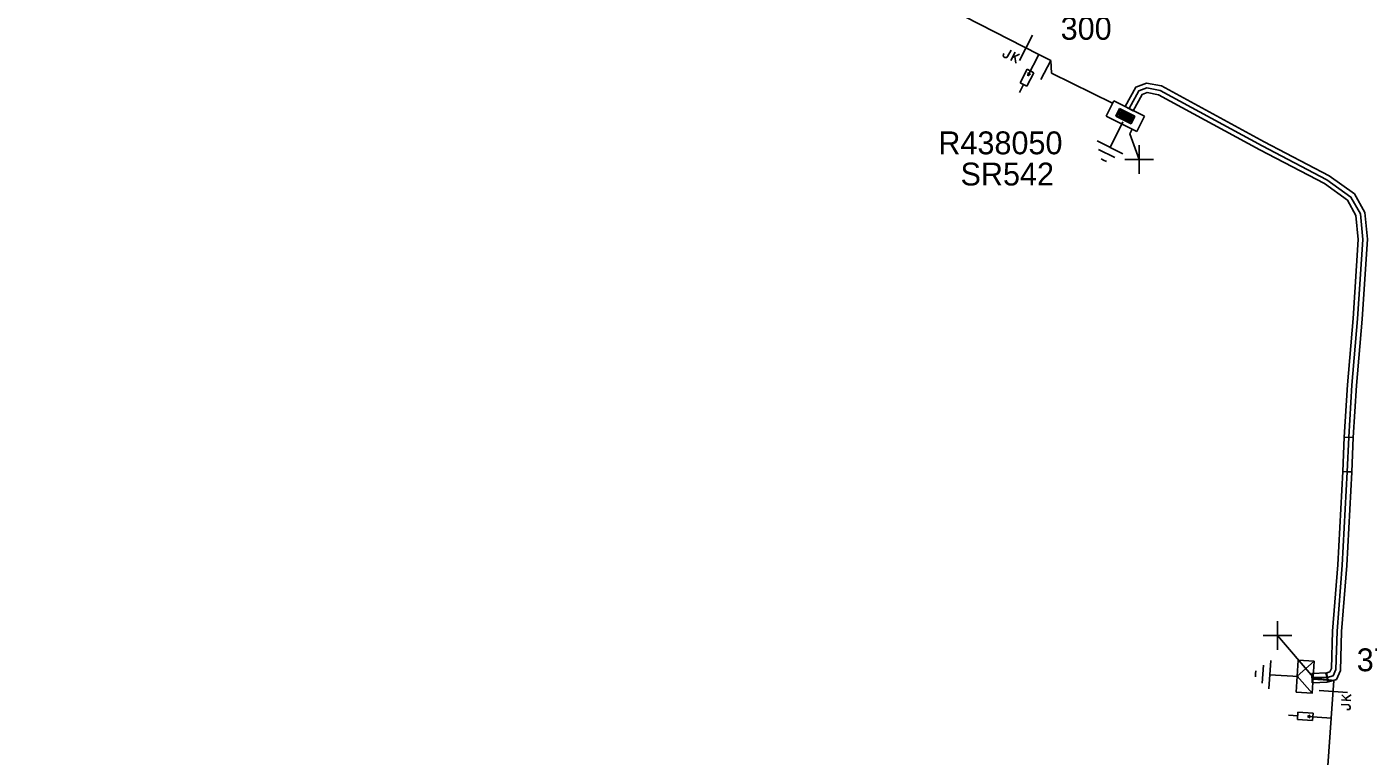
# Model space of a CAD drawing. Extents: x -540466 to -537383, y -1184038 to -1179972.
# Drawn here: x -537995.3 to -537936.6, y -1180751.6 to -1180719.7 of the extents above; entities that cross this region are included whole.
import ezdxf

# ---------------------------------------------------------------- set-up
doc = ezdxf.new("R2010")
doc.units = 0
for name, color, linetype in [('Vrstva 1', 7, 'Continuous'), ('Vrstva 13', 7, 'Continuous'), ('Vrstva 14', 7, 'Continuous'), ('Vrstva 15', 7, 'Continuous'), ('Vrstva 16', 7, 'Continuous'), ('Vrstva 18', 7, 'Continuous'), ('Vrstva 2', 7, 'Continuous'), ('Vrstva 20', 7, 'Continuous'), ('Vrstva 28', 7, 'Continuous'), ('Vrstva 29', 7, 'Continuous'), ('Vrstva 30', 7, 'Continuous'), ('Vrstva 31', 7, 'Continuous'), ('Vrstva 34', 7, 'Continuous'), ('Vrstva 5', 7, 'Continuous'), ('Vrstva 50', 7, 'Continuous'), ('Vrstva 59', 7, 'Continuous'), ('Vrstva 8', 7, 'Continuous'), ('Vrstva 9', 7, 'Continuous')]:
    doc.layers.add(name, color=color, linetype=linetype)

# ---------------------------------------------------------------- blocks, each defined once
blk = doc.blocks.new('NN840')
at = {"layer": 'Vrstva 15'}
for points in [[(0.003, 0.619), (0.003, -0.631)], [(-0.538, -0.385), (-0.538, -0.71)], [(-0.332, -0.385), (-0.332, -0.798)], [(-0.332, -0.641), (-0.125, -0.385)], [(-0.263, -0.557), (-0.091, -0.798)], [(-0.745, -0.71), (-0.745, -0.66)], [(-0.73, -0.764), (-0.745, -0.71)], [(-0.657, -0.798), (-0.73, -0.764)], [(-0.627, -0.798), (-0.657, -0.798)], [(-0.558, -0.764), (-0.627, -0.798)], [(-0.538, -0.71), (-0.558, -0.764)]]:
    blk.add_lwpolyline(points, dxfattribs=at)
blk = doc.blocks.new('NN800')
at = {"layer": 'Vrstva 1'}
for points in [[(-0.442, 0.442), (0.442, -0.442)], [(-0.442, -0.442), (0.442, 0.442)]]:
    blk.add_lwpolyline(points, dxfattribs=at)
blk = doc.blocks.new('NN820')
at = {"layer": 'Vrstva 13'}
for points in [[(-0.003, 0.004), (-0.003, -1.049)], [(-0.165, -0.813), (0.165, -0.813)], [(-0.165, -1.473), (-0.165, -0.813)], [(-0.003, -1.049), (-0.062, -0.926)], [(-0.003, -1.049), (0.057, -0.926)], [(0.165, -0.813), (0.165, -1.473)], [(0.165, -1.473), (-0.165, -1.473)], [(-0.003, -1.473), (-0.003, -1.871)]]:
    blk.add_lwpolyline(points, dxfattribs=at)
blk = doc.blocks.new('NN620')
at = {"layer": 'Vrstva 8'}
for points in [[(0.752, 0.004), (-0.748, 0.004)], [(-0.748, 0.004), (-0.748, -0.746)], [(0.752, -0.746), (0.752, 0.004)], [(0.368, -0.18), (-0.376, -0.18)], [(-0.376, -0.18), (-0.376, -0.558)], [(-0.376, -0.558), (0.368, -0.558)], [(0.321, -0.227), (-0.329, -0.227)], [(-0.329, -0.227), (-0.329, -0.51)], [(-0.329, -0.51), (0.321, -0.51)], [(0.274, -0.274), (-0.281, -0.274)], [(-0.281, -0.274), (-0.281, -0.463)], [(-0.281, -0.463), (0.274, -0.463)], [(0.227, -0.321), (-0.234, -0.321)], [(-0.234, -0.321), (-0.234, -0.416)], [(-0.234, -0.416), (0.227, -0.416)], [(-0.193, -0.369), (0.185, -0.369)], [(0.227, -0.416), (0.227, -0.321)], [(0.274, -0.463), (0.274, -0.274)], [(0.321, -0.51), (0.321, -0.227)], [(0.368, -0.558), (0.368, -0.18)], [(-0.748, -0.746), (0.752, -0.746)]]:
    blk.add_lwpolyline(points, dxfattribs=at)
blk = doc.blocks.new('NN630')
at = {"layer": 'Vrstva 9'}
for points in [[(-0.003, -0.7), (-0.703, 0)], [(-0.703, -0.7), (-0.703, 0), (0.697, 0), (0.697, -0.7)], [(-0.003, -0.7), (0.697, 0)], [(-0.703, -0.7), (0.697, -0.7)]]:
    blk.add_lwpolyline(points, dxfattribs=at)
blk = doc.blocks.new('NN810')
at = {"layer": 'Vrstva 14'}
for points in [[(0.004, -0.64), (0.004, -1.89)], [(0.629, -1.89), (-0.621, -1.89)], [(0.388, -2.2), (-0.399, -2.2)], [(0.004, -2.515), (-0.124, -2.515)], [(0.137, -2.515), (0.004, -2.515)]]:
    blk.add_lwpolyline(points, dxfattribs=at)
blk = doc.blocks.new('NN510')
at = {"layer": 'Vrstva 2'}
blk.add_lwpolyline([(0.001, 0.002), (0.001, 0.939)], dxfattribs=at)

msp = doc.modelspace()

# ---------------------------------------------------------------- linework, layer by layer
at = {"layer": 'Vrstva 20'}
for points in [[(-537945.642, -1180722.279), (-537941.156, -1180724.724), (-537938.315, -1180726.209), (-537937.207, -1180727.004), (-537936.755, -1180727.819), (-537936.639, -1180728.987), (-537936.871, -1180732.485), (-537937.121, -1180735.385), (-537937.26, -1180737.662), (-537937.66, -1180737.638), (-537937.519, -1180735.355), (-537937.269, -1180732.455), (-537937.041, -1180728.993), (-537937.145, -1180727.941), (-537937.513, -1180727.276), (-537938.525, -1180726.551), (-537941.344, -1180725.076), (-537945.778, -1180722.661), (-537946.272, -1180722.567), (-537946.49, -1180722.651), (-537946.885, -1180723.367), (-537947.235, -1180723.173), (-537946.77, -1180722.329), (-537946.308, -1180722.153)], [(-537937.72, -1180739.152), (-537937.66, -1180737.642), (-537937.26, -1180737.658), (-537937.32, -1180739.168)], [(-537938.17, -1180746.129), (-537937.94, -1180743.227), (-537937.72, -1180739.149), (-537937.32, -1180739.171), (-537937.54, -1180743.253), (-537937.77, -1180746.151), (-537937.821, -1180747.855), (-537937.994, -1180748.244), (-537938.341, -1180748.351), (-537938.459, -1180747.969), (-537938.286, -1180747.916), (-537938.219, -1180747.765)], [(-537939.069, -1180747.99), (-537938.409, -1180747.96), (-537938.391, -1180748.36), (-537939.051, -1180748.39)]]:
    msp.add_lwpolyline(points, close=True, dxfattribs=at)
at = {"layer": 'Vrstva 5'}
for points in [[(-537950.479, -1180721.169), (-537950.455, -1180721.718), (-537947.782, -1180723.033)], [(-537947.06, -1180723.27), (-537946.63, -1180722.49), (-537946.29, -1180722.36), (-537945.71, -1180722.47), (-537941.25, -1180724.9), (-537938.42, -1180726.38), (-537937.36, -1180727.14), (-537936.95, -1180727.88), (-537936.84, -1180728.99), (-537937.07, -1180732.47), (-537937.32, -1180735.37), (-537937.46, -1180737.65), (-537937.52, -1180739.16), (-537937.74, -1180743.24), (-537937.97, -1180746.14), (-537938.02, -1180747.81), (-537938.14, -1180748.08), (-537938.4, -1180748.16), (-537939.02, -1180748.15)], [(-537938.107, -1180748.294), (-537938.96, -1180748.182), (-537939.02, -1180748.15)]]:
    msp.add_lwpolyline(points, dxfattribs=at)
at = {"layer": 'Vrstva 50'}
for points in [[(-538071.256, -1180615.16), (-538046.58, -1180650.51), (-538023.749, -1180683.259), (-538014.349, -1180688.199), (-538006.46, -1180692.14), (-538002.47, -1180694.22), (-537989.149, -1180701.079), (-537980.6, -1180705.81), (-537975.799, -1180708.289), (-537962.429, -1180714.939), (-537958.79, -1180716.9), (-537951.004, -1180720.901), (-537950.48, -1180721.17)], [(-537938.107, -1180748.294), (-537938.221, -1180749.937), (-537938.966, -1180760.566), (-537939.537, -1180773.452), (-537940.318, -1180782.553), (-537941.765, -1180795.073)]]:
    msp.add_lwpolyline(points, dxfattribs=at)
at = {"layer": 'Vrstva 59'}
for points in [[(-537946.932, -1180724.17), (-537947.024, -1180724.376), (-537946.628, -1180725.495)], [(-537939.02, -1180748.15), (-537940.571, -1180746.327)]]:
    msp.add_lwpolyline(points, dxfattribs=at)

# ---------------------------------------------------------------- block references
at = {"layer": 'Vrstva 13'}
for p, rotation in [((-537950.479, -1180721.169), 151.94587219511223), ((-537938.107, -1180748.295), 86.2161083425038)]:
    msp.add_blockref('NN510', p, dxfattribs=dict(at, rotation=rotation))
at = {"layer": 'Vrstva 15'}
for p, rotation in [((-537947.06, -1180723.27), -26.42498894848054), ((-537939.02, -1180748.15), -93.54988052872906)]:
    msp.add_blockref('NN810', p, dxfattribs=dict(at, rotation=rotation))
at = {"layer": 'Vrstva 16'}
for p, rotation in [((-537951.004, -1180720.901), -27.19585560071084), ((-537938.221, -1180749.937), -93.98081664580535)]:
    msp.add_blockref('NN820', p, dxfattribs=dict(at, rotation=rotation))
at = {"layer": 'Vrstva 18'}
for p, rotation in [((-537951.571, -1180720.609), -27.195855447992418), ((-537938.141, -1180748.774), 85.99601390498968)]:
    msp.add_blockref('NN840', p, dxfattribs=dict(at, rotation=rotation))
at = {"layer": 'Vrstva 28', "rotation": -26.42498894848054}
msp.add_blockref('NN620', (-537947.06, -1180723.27), dxfattribs=at)
at = {"layer": 'Vrstva 31', "rotation": -93.5498805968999}
msp.add_blockref('NN630', (-537939.02, -1180748.15), dxfattribs=at)
at = {"layer": 'Vrstva 34', "rotation": 45}
for p in [(-537946.628, -1180725.495), (-537940.571, -1180746.327)]:
    msp.add_blockref('NN800', p, dxfattribs=at)

# ---------------------------------------------------------------- texts
at = {"layer": 'Vrstva 14'}
for s, p in [('300', (-537950.055, -1180720.257)), ('370', (-537937.109, -1180747.887))]:
    msp.add_text(s, height=1, dxfattribs=at).set_placement(p)
at = {"layer": 'Vrstva 29'}
msp.add_text('R438050', height=1, dxfattribs=at).set_placement((-537955.404, -1180725.268))
at = {"layer": 'Vrstva 30'}
msp.add_text('SR542', height=1, dxfattribs=at).set_placement((-537954.435, -1180726.633))

doc.saveas('drawing.dxf')
